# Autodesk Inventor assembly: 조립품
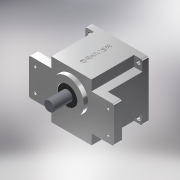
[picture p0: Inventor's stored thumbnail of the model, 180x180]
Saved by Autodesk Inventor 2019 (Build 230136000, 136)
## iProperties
Created: 2020-07
Part Number: 조립품
Material: 일반
Document SubType Name: Assembly
Designer: Admin
Author: Admin
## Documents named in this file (10)
- C:\Users\Admin\Desktop\700707V1016\조립품.iam
- C:\Users\Admin\Desktop\700707V1016\본체.ipt
- C:\Users\Admin\Desktop\700707V1016\커버.ipt
- C:\Users\Admin\Desktop\700707V1016\메인 축.ipt
- C:\Users\Admin\Desktop\700707V1016\서브 축.ipt
- C:\Users\Admin\Desktop\700707V1016\볼트 M4.ipt
- C:\Users\Admin\Desktop\700707V1016\베어링 6003.ipt
- C:\Users\Admin\Desktop\700707V1016\베어링 608.ipt
- C:\Users\Admin\Desktop\700707V1016\오일 실 17 32 8.ipt
- C:\Users\Admin\Desktop\700707V1016\오일 실 8 22 7.ipt
